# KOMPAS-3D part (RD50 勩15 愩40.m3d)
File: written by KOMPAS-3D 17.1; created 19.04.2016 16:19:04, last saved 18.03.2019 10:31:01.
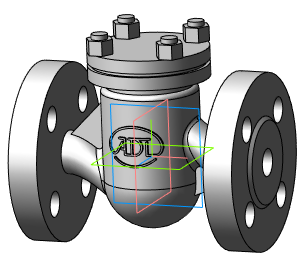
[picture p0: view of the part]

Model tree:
1. Операция без истории:2  (labels: Сталь 20  ГОСТ 1050-88)

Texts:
  RD50 Ду15 Ру40
  RD50 Ду20 Ру40
  RD50 Ду25 Ру40
  RD50 Ду32 Ру40
  RD50 Ду40 Ру40
  RD50 Ду50 Ру40
  RD50 Ду65 Ру40
  RD50 Ду80 Ру40
  RD50 Ду100 Ру40
  RD50 Ду125 Ру40
  RD50 Ду150 Ру40
  RD50 Ду200 Ру40
  RD50 Ду250 Ру40
  RD50 Ду300 Ру40
  RD50 Ду350 Ру40
  RD50 Ду400 Ру40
